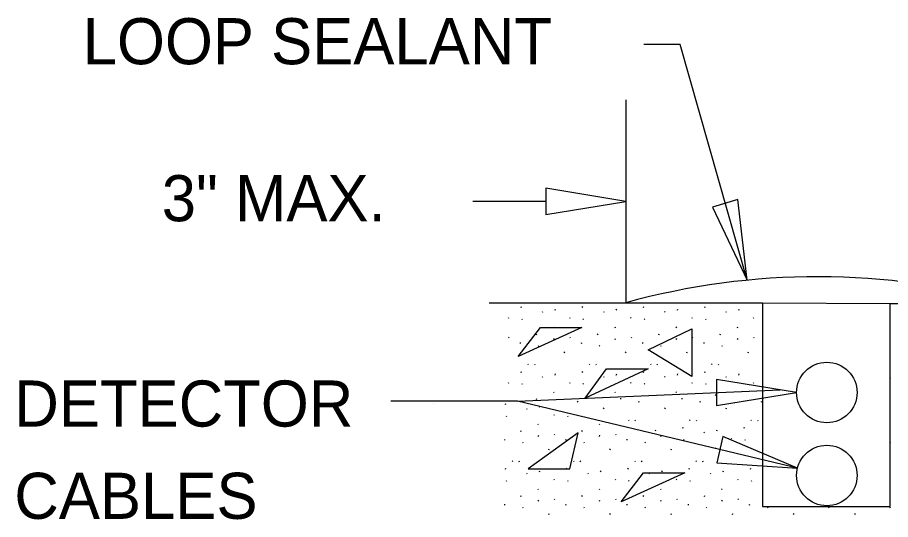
# Model space of a CAD drawing. Extents: x -1550.42 to -1543.2, y 2481.09 to 2491.
# Drawn here: x -1549.591 to -1548.454, y 2486.574 to 2487.227 of the extents above; entities that cross this region are included whole.
import ezdxf

# ---------------------------------------------------------------- set-up
doc = ezdxf.new("R2010")
doc.units = 0
for name, color, linetype in [('DETL-DIMS', 7, 'Continuous'), ('DETL-LINE', 7, 'Continuous'), ('DETL-NOTE', 7, 'Continuous'), ('DETL-PATT', 7, 'Continuous')]:
    doc.layers.add(name, color=color, linetype=linetype)

msp = doc.modelspace()

# ---------------------------------------------------------------- linework, layer by layer
at = {"layer": 'DETL-DIMS'}
for p, q in [((-1548.7284, 2487.192), (-1548.7754, 2487.192)), ((-1548.6411, 2486.8854), (-1548.7284, 2487.192)), ((-1548.799, 2487.12), (-1548.799, 2486.856)), ((-1548.903, 2486.988), (-1548.998, 2486.988)), ((-1548.94, 2486.728), (-1548.598, 2486.743)), ((-1548.94, 2486.728), (-1549.105, 2486.728)), ((-1548.5755, 2486.641), (-1548.94, 2486.728)), ((-1548.658, 2486.725), (-1548.658, 2486.725))]:
    msp.add_line(p, q, dxfattribs=at)
for points in [[(-1548.903, 2487.005), (-1548.903, 2486.971), (-1548.799, 2486.988)], [(-1548.6531, 2486.9904), (-1548.6861, 2486.9804), (-1548.6411, 2486.8854)], [(-1548.6807, 2486.7564), (-1548.6807, 2486.7224), (-1548.5767, 2486.7394)], [(-1548.6725, 2486.682), (-1548.6805, 2486.648), (-1548.5755, 2486.641)]]:
    msp.add_lwpolyline(points, close=True, dxfattribs=at)
at = {"layer": 'DETL-LINE'}
for p, q in [((-1548.977, 2486.856), (-1548.621, 2486.856)), ((-1548.918, 2486.855), (-1548.918, 2486.855)), ((-1548.853, 2486.855), (-1548.853, 2486.855)), ((-1548.788, 2486.855), (-1548.788, 2486.855)), ((-1548.723, 2486.855), (-1548.723, 2486.855)), ((-1548.621, 2486.856), (-1548.621, 2486.591)), ((-1548.621, 2486.856), (-1548.455, 2486.855)), ((-1548.455, 2486.855), (-1548.1162, 2486.855)), ((-1548.455, 2486.591), (-1548.455, 2486.855)), ((-1548.625, 2486.66), (-1548.625, 2486.66)), ((-1548.528, 2486.595), (-1548.528, 2486.595)), ((-1548.621, 2486.591), (-1548.455, 2486.591))]:
    msp.add_line(p, q, dxfattribs=at)
for centre in [(-1548.5373, 2486.7394), (-1548.5373, 2486.6314)]:
    msp.add_circle(centre, 0.0394, dxfattribs=at)
msp.add_arc((-1548.5493, 2485.9521), 0.9378, 74.3295, 105.4426, dxfattribs=at)
at = {"layer": 'DETL-PATT'}
for p, q in [((-1548.9353, 2486.8499), (-1548.9347, 2486.8512)), ((-1548.8911, 2486.8464), (-1548.8905, 2486.8478)), ((-1548.8556, 2486.8499), (-1548.855, 2486.8512)), ((-1548.8114, 2486.8464), (-1548.8108, 2486.8478)), ((-1548.7759, 2486.8499), (-1548.7753, 2486.8512)), ((-1548.7317, 2486.8464), (-1548.7311, 2486.8478)), ((-1548.6962, 2486.8499), (-1548.6956, 2486.8512)), ((-1548.652, 2486.8464), (-1548.6514, 2486.8478)), ((-1548.9521, 2486.8369), (-1548.9515, 2486.836)), ((-1548.9344, 2486.8352), (-1548.9338, 2486.8343)), ((-1548.9079, 2486.8447), (-1548.9073, 2486.8438)), ((-1548.8724, 2486.8369), (-1548.8718, 2486.836)), ((-1548.8547, 2486.8352), (-1548.8541, 2486.8343)), ((-1548.8282, 2486.8447), (-1548.8276, 2486.8438)), ((-1548.7927, 2486.8369), (-1548.7921, 2486.836)), ((-1548.775, 2486.8352), (-1548.7744, 2486.8343)), ((-1548.7485, 2486.8447), (-1548.7479, 2486.8438)), ((-1548.713, 2486.8369), (-1548.7124, 2486.836)), ((-1548.6952, 2486.8352), (-1548.6946, 2486.8343)), ((-1548.6687, 2486.8447), (-1548.6681, 2486.8438)), ((-1548.6332, 2486.8369), (-1548.6326, 2486.836)), ((-1548.939, 2486.786), (-1548.91, 2486.824)), ((-1548.856, 2486.824), (-1548.939, 2486.786)), ((-1548.91, 2486.824), (-1548.856, 2486.824)), ((-1548.8931, 2486.8246), (-1548.8925, 2486.8237)), ((-1548.8134, 2486.8246), (-1548.8128, 2486.8237)), ((-1548.7337, 2486.8246), (-1548.7331, 2486.8237)), ((-1548.654, 2486.8246), (-1548.6534, 2486.8237)), ((-1548.9515, 2486.8113), (-1548.9509, 2486.8104)), ((-1548.9154, 2486.8145), (-1548.9148, 2486.8159)), ((-1548.8718, 2486.8113), (-1548.8712, 2486.8104)), ((-1548.8357, 2486.8145), (-1548.8351, 2486.8159)), ((-1548.7921, 2486.8113), (-1548.7915, 2486.8104)), ((-1548.77, 2486.795), (-1548.713, 2486.822)), ((-1548.756, 2486.8145), (-1548.7554, 2486.8159)), ((-1548.714, 2486.822), (-1548.714, 2486.822)), ((-1548.713, 2486.822), (-1548.713, 2486.76)), ((-1548.7124, 2486.8113), (-1548.7118, 2486.8104)), ((-1548.6762, 2486.8145), (-1548.6756, 2486.8159)), ((-1548.6327, 2486.8113), (-1548.6321, 2486.8104)), ((-1548.9367, 2486.8046), (-1548.9366, 2486.8033)), ((-1548.9132, 2486.8006), (-1548.9126, 2486.7997)), ((-1548.8926, 2486.8084), (-1548.892, 2486.8097)), ((-1548.857, 2486.8046), (-1548.8568, 2486.8033)), ((-1548.8335, 2486.8006), (-1548.8329, 2486.7997)), ((-1548.8129, 2486.8084), (-1548.8123, 2486.8097)), ((-1548.7773, 2486.8046), (-1548.7771, 2486.8033)), ((-1548.7538, 2486.8006), (-1548.7532, 2486.7997)), ((-1548.7332, 2486.8084), (-1548.7326, 2486.8097)), ((-1548.6976, 2486.8046), (-1548.6974, 2486.8033)), ((-1548.6741, 2486.8006), (-1548.6735, 2486.7997)), ((-1548.6535, 2486.8084), (-1548.6529, 2486.8097)), ((-1548.879, 2486.791), (-1548.8784, 2486.7923)), ((-1548.7993, 2486.791), (-1548.7987, 2486.7923)), ((-1548.713, 2486.76), (-1548.77, 2486.795)), ((-1548.7195, 2486.791), (-1548.7189, 2486.7923)), ((-1548.6398, 2486.791), (-1548.6392, 2486.7923)), ((-1548.9353, 2486.7656), (-1548.9347, 2486.7669)), ((-1548.9265, 2486.7767), (-1548.9259, 2486.7758)), ((-1548.9179, 2486.7763), (-1548.9173, 2486.7754)), ((-1548.8556, 2486.7656), (-1548.855, 2486.7669)), ((-1548.852, 2486.732), (-1548.824, 2486.77)), ((-1548.77, 2486.77), (-1548.852, 2486.732)), ((-1548.8468, 2486.7767), (-1548.8462, 2486.7758)), ((-1548.8382, 2486.7763), (-1548.8376, 2486.7754)), ((-1548.824, 2486.77), (-1548.77, 2486.77)), ((-1548.7759, 2486.7656), (-1548.7753, 2486.7669)), ((-1548.767, 2486.7767), (-1548.7664, 2486.7758)), ((-1548.7585, 2486.7763), (-1548.7579, 2486.7754)), ((-1548.6962, 2486.7656), (-1548.6956, 2486.7669)), ((-1548.6873, 2486.7767), (-1548.6867, 2486.7758)), ((-1548.6788, 2486.7763), (-1548.6782, 2486.7754)), ((-1548.9079, 2486.7604), (-1548.9073, 2486.7595)), ((-1548.8911, 2486.7621), (-1548.8905, 2486.7635)), ((-1548.8282, 2486.7604), (-1548.8276, 2486.7595)), ((-1548.8114, 2486.7621), (-1548.8108, 2486.7635)), ((-1548.7485, 2486.7604), (-1548.7479, 2486.7595)), ((-1548.7317, 2486.7621), (-1548.7311, 2486.7635)), ((-1548.681, 2486.757), (-1548.681, 2486.757)), ((-1548.6687, 2486.7604), (-1548.6681, 2486.7595)), ((-1548.652, 2486.7621), (-1548.6514, 2486.7635)), ((-1548.455, 2486.7585), (-1548.4547, 2486.758)), ((-1548.9521, 2486.7525), (-1548.9515, 2486.7516)), ((-1548.9344, 2486.7509), (-1548.9338, 2486.75)), ((-1548.8724, 2486.7525), (-1548.8718, 2486.7516)), ((-1548.8547, 2486.7509), (-1548.8541, 2486.75)), ((-1548.7927, 2486.7525), (-1548.7921, 2486.7516)), ((-1548.775, 2486.7509), (-1548.7744, 2486.75)), ((-1548.713, 2486.7525), (-1548.7124, 2486.7516)), ((-1548.6952, 2486.7509), (-1548.6946, 2486.75)), ((-1548.6332, 2486.7525), (-1548.6326, 2486.7516)), ((-1548.9154, 2486.7302), (-1548.9148, 2486.7316)), ((-1548.8931, 2486.7403), (-1548.8925, 2486.7394)), ((-1548.8134, 2486.7403), (-1548.8128, 2486.7394)), ((-1548.8059, 2486.7318), (-1548.8057, 2486.7305)), ((-1548.7618, 2486.7356), (-1548.7617, 2486.7358)), ((-1548.7337, 2486.7403), (-1548.7331, 2486.7394)), ((-1548.7261, 2486.7318), (-1548.726, 2486.7305)), ((-1548.6821, 2486.7356), (-1548.6815, 2486.737)), ((-1549.049, 2486.725), (-1549.049, 2486.725)), ((-1548.9557, 2486.7238), (-1548.9551, 2486.7252)), ((-1548.918, 2486.725), (-1548.918, 2486.725)), ((-1548.9115, 2486.7204), (-1548.9111, 2486.7211)), ((-1548.8621, 2486.7279), (-1548.8615, 2486.727)), ((-1548.7824, 2486.7279), (-1548.7818, 2486.727)), ((-1548.7027, 2486.7279), (-1548.7021, 2486.727)), ((-1548.6229, 2486.7279), (-1548.6223, 2486.727)), ((-1548.9547, 2486.7092), (-1548.9541, 2486.7083)), ((-1548.9282, 2486.7186), (-1548.9276, 2486.7177)), ((-1548.8927, 2486.7108), (-1548.8921, 2486.7099)), ((-1548.875, 2486.7092), (-1548.8744, 2486.7083)), ((-1548.8279, 2486.7182), (-1548.8273, 2486.7196)), ((-1548.7481, 2486.7182), (-1548.7475, 2486.7196)), ((-1548.6684, 2486.7182), (-1548.6678, 2486.7196)), ((-1548.9135, 2486.6985), (-1548.9129, 2486.6976)), ((-1548.8337, 2486.6985), (-1548.8331, 2486.6976)), ((-1548.7956, 2486.7039), (-1548.795, 2486.703)), ((-1548.7871, 2486.7036), (-1548.7865, 2486.7027)), ((-1548.7159, 2486.7039), (-1548.7153, 2486.703)), ((-1548.7074, 2486.7036), (-1548.7068, 2486.7027)), ((-1548.6362, 2486.7039), (-1548.6356, 2486.703)), ((-1548.6277, 2486.7036), (-1548.6271, 2486.7027)), ((-1548.9357, 2486.6885), (-1548.9351, 2486.6898)), ((-1548.861, 2486.687), (-1548.926, 2486.64)), ((-1548.872, 2486.64), (-1548.861, 2486.687)), ((-1548.856, 2486.6885), (-1548.8554, 2486.6898)), ((-1548.7763, 2486.6885), (-1548.7761, 2486.6889)), ((-1548.7603, 2486.6894), (-1548.7597, 2486.6907)), ((-1548.7248, 2486.6928), (-1548.7242, 2486.6941)), ((-1548.6973, 2486.6876), (-1548.6967, 2486.6867)), ((-1548.6806, 2486.6894), (-1548.68, 2486.6907)), ((-1548.645, 2486.6928), (-1548.6444, 2486.6941)), ((-1548.957, 2486.6784), (-1548.9569, 2486.6772)), ((-1548.9336, 2486.6746), (-1548.933, 2486.6737)), ((-1548.913, 2486.6823), (-1548.9124, 2486.6837)), ((-1548.8922, 2486.6852), (-1548.8916, 2486.6843)), ((-1548.8773, 2486.6786), (-1548.8772, 2486.6772)), ((-1548.8538, 2486.6746), (-1548.8532, 2486.6737)), ((-1548.8332, 2486.6823), (-1548.8326, 2486.6837)), ((-1548.8125, 2486.6852), (-1548.8119, 2486.6843)), ((-1548.7976, 2486.6786), (-1548.7975, 2486.6772)), ((-1548.7741, 2486.6746), (-1548.7735, 2486.6737)), ((-1548.7535, 2486.6823), (-1548.7531, 2486.6834)), ((-1548.7238, 2486.6781), (-1548.7232, 2486.6772)), ((-1548.6618, 2486.6798), (-1548.6612, 2486.6789)), ((-1548.6441, 2486.6781), (-1548.6435, 2486.6772)), ((-1548.8993, 2486.6649), (-1548.8987, 2486.6663)), ((-1548.8196, 2486.6649), (-1548.819, 2486.6663)), ((-1548.7399, 2486.6649), (-1548.7393, 2486.6663)), ((-1548.6825, 2486.6675), (-1548.6819, 2486.6666)), ((-1548.455, 2486.6742), (-1548.4547, 2486.6737)), ((-1548.9557, 2486.6395), (-1548.9551, 2486.6409)), ((-1548.9468, 2486.6506), (-1548.9462, 2486.6497)), ((-1548.9383, 2486.6503), (-1548.9377, 2486.6494)), ((-1548.876, 2486.6395), (-1548.8754, 2486.6409)), ((-1548.8671, 2486.6506), (-1548.8665, 2486.6497)), ((-1548.8586, 2486.6503), (-1548.858, 2486.6494)), ((-1548.7962, 2486.6395), (-1548.7956, 2486.6409)), ((-1548.7874, 2486.6506), (-1548.7868, 2486.6497)), ((-1548.7789, 2486.6503), (-1548.7783, 2486.6494)), ((-1548.7165, 2486.6395), (-1548.7159, 2486.6409)), ((-1548.7077, 2486.6506), (-1548.7071, 2486.6497)), ((-1548.6991, 2486.6503), (-1548.6985, 2486.6494)), ((-1548.6368, 2486.6395), (-1548.6362, 2486.6409)), ((-1548.9282, 2486.6343), (-1548.9276, 2486.6334)), ((-1548.926, 2486.64), (-1548.872, 2486.64)), ((-1548.9115, 2486.6361), (-1548.9109, 2486.6374)), ((-1548.8485, 2486.6343), (-1548.8479, 2486.6334)), ((-1548.8318, 2486.6361), (-1548.8312, 2486.6374)), ((-1548.722, 2486.635), (-1548.805, 2486.597)), ((-1548.805, 2486.597), (-1548.776, 2486.635)), ((-1548.776, 2486.635), (-1548.722, 2486.635)), ((-1548.7688, 2486.6343), (-1548.7682, 2486.6334)), ((-1548.752, 2486.6361), (-1548.7514, 2486.6374)), ((-1548.6891, 2486.6343), (-1548.6885, 2486.6334)), ((-1548.6723, 2486.6361), (-1548.6717, 2486.6374)), ((-1548.9547, 2486.6249), (-1548.9541, 2486.624)), ((-1548.8927, 2486.6265), (-1548.8921, 2486.6256)), ((-1548.875, 2486.6249), (-1548.8744, 2486.624)), ((-1548.813, 2486.6265), (-1548.8124, 2486.6256)), ((-1548.7953, 2486.6249), (-1548.7947, 2486.624)), ((-1548.7333, 2486.6265), (-1548.7327, 2486.6256)), ((-1548.7156, 2486.6249), (-1548.715, 2486.624)), ((-1548.6536, 2486.6265), (-1548.653, 2486.6256)), ((-1548.6359, 2486.6249), (-1548.6353, 2486.624)), ((-1548.9135, 2486.6142), (-1548.9129, 2486.6133)), ((-1548.8337, 2486.6142), (-1548.8331, 2486.6133)), ((-1548.754, 2486.6142), (-1548.7534, 2486.6133)), ((-1548.6743, 2486.6142), (-1548.6737, 2486.6133)), ((-1548.9357, 2486.6042), (-1548.9351, 2486.6055)), ((-1548.913, 2486.598), (-1548.9124, 2486.5994)), ((-1548.8922, 2486.6009), (-1548.8916, 2486.6)), ((-1548.856, 2486.6042), (-1548.8554, 2486.6055)), ((-1548.8332, 2486.598), (-1548.8326, 2486.5994)), ((-1548.8125, 2486.6009), (-1548.8119, 2486.6)), ((-1548.7763, 2486.6042), (-1548.7757, 2486.6055)), ((-1548.7535, 2486.598), (-1548.7529, 2486.5994)), ((-1548.7327, 2486.6009), (-1548.7321, 2486.6)), ((-1548.6966, 2486.6042), (-1548.696, 2486.6055)), ((-1548.6738, 2486.598), (-1548.6732, 2486.5994)), ((-1548.653, 2486.6009), (-1548.6524, 2486.6)), ((-1548.957, 2486.5941), (-1548.9569, 2486.5929)), ((-1548.9336, 2486.5903), (-1548.933, 2486.5894)), ((-1548.8773, 2486.5942), (-1548.8772, 2486.5929)), ((-1548.8538, 2486.5903), (-1548.8532, 2486.5894)), ((-1548.7976, 2486.5942), (-1548.7975, 2486.5929)), ((-1548.7741, 2486.5903), (-1548.7735, 2486.5894)), ((-1548.7179, 2486.5942), (-1548.7178, 2486.5929)), ((-1548.6944, 2486.5903), (-1548.6938, 2486.5894)), ((-1548.6382, 2486.5942), (-1548.638, 2486.5929)), ((-1548.6147, 2486.5903), (-1548.6141, 2486.5894)), ((-1548.535, 2486.5903), (-1548.5344, 2486.5894)), ((-1548.4553, 2486.5903), (-1548.4547, 2486.5894)), ((-1548.8993, 2486.5806), (-1548.8987, 2486.582)), ((-1548.8196, 2486.5806), (-1548.819, 2486.582)), ((-1548.7399, 2486.5806), (-1548.7393, 2486.582)), ((-1548.6602, 2486.5806), (-1548.6596, 2486.582)), ((-1548.5805, 2486.5806), (-1548.5799, 2486.582)), ((-1548.5007, 2486.5806), (-1548.5001, 2486.582))]:
    msp.add_line(p, q, dxfattribs=at)

# ---------------------------------------------------------------- texts
at = {"layer": 'DETL-NOTE'}
for s, p in [('LOOP SEALANT', (-1549.506, 2487.1663)), ('3" MAX.', (-1549.4031, 2486.9621)), ('DETECTOR', (-1549.595, 2486.695)), ('CABLES', (-1549.595, 2486.575))]:
    msp.add_text(s, height=0.06, dxfattribs=at).set_placement(p)

doc.saveas('drawing.dxf')
